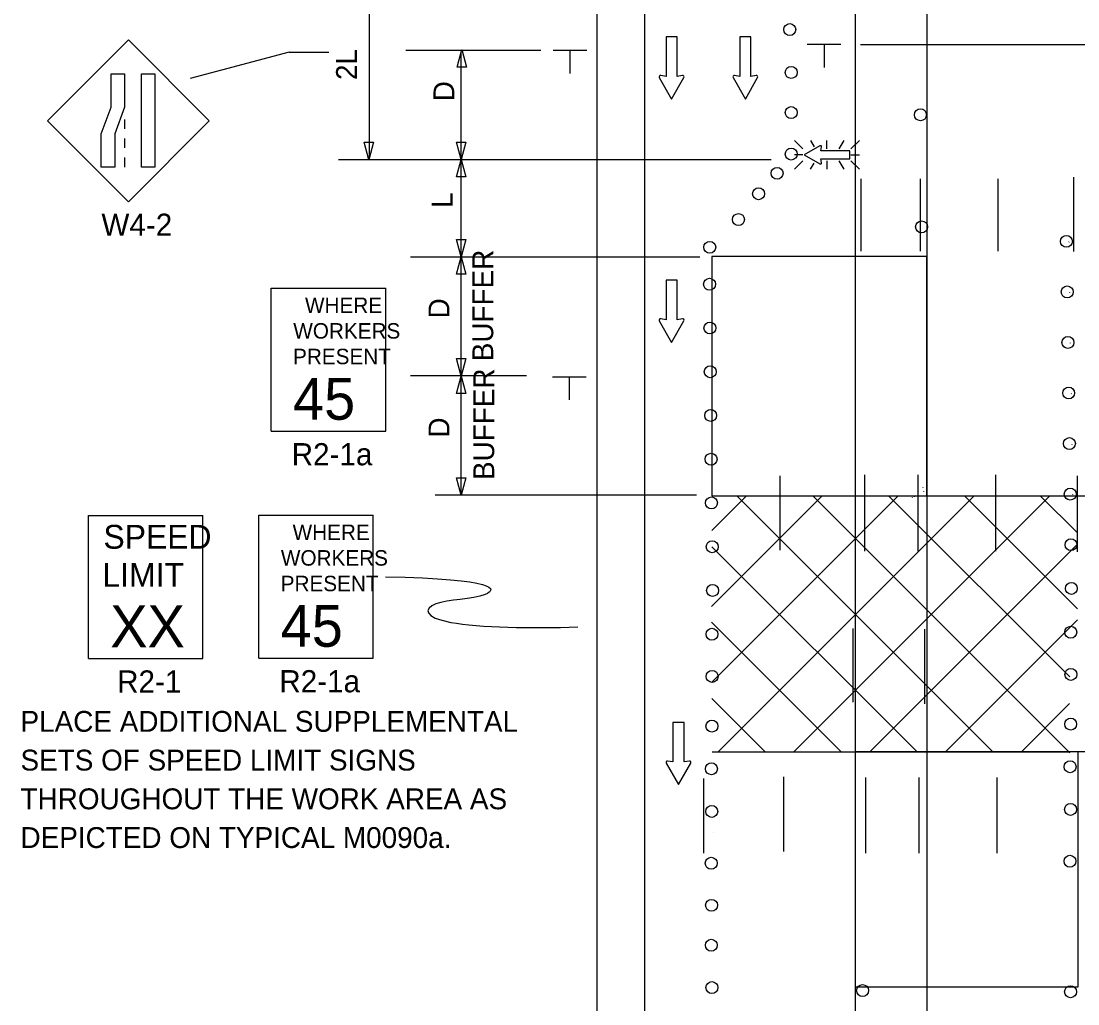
# Model space of a CAD drawing. Extents: x 20837 to 23689, y 414 to 2167.
# Drawn here: x 20920.2 to 21274.8, y 982.6 to 1312.5 of the extents above; entities that cross this region are included whole.
import ezdxf

# ---------------------------------------------------------------- set-up
doc = ezdxf.new("R2010")
doc.units = 0
for name, color, linetype in [('ALI_LEGAL_EX', 7, 'Continuous'), ('MT_SCRATCH_LEVEL_A', 7, 'Continuous'), ('MT_SCRATCH_LEVEL_E', 7, 'Continuous'), ('PAVT_EDGE_EX', 7, 'Continuous'), ('TRAFFIC_SIGNS_PR', 7, 'Continuous'), ('TYPICAL_EX', 7, 'Continuous'), ('TYPICAL_TEXT_DIMEN_PR', 7, 'Continuous')]:
    doc.layers.add(name, color=color, linetype=linetype)

msp = doc.modelspace()

# ---------------------------------------------------------------- linework, layer by layer
at = {"layer": 'ALI_LEGAL_EX'}
for points in [[(21202.17, 1235.29), (21202.17, 1259.59)], [(21222.04, 1235.29), (21222.04, 1259.59)], [(21248.14, 1235.29), (21248.14, 1259.59)], [(21273.46, 1235.24), (21273.46, 1260.18)], [(21174.97, 1134.9), (21174.97, 1159.91)], [(21203.3, 1134.6), (21203.3, 1160.28)], [(21221.19, 1134.6), (21221.19, 1160.28)], [(21247.3, 1134.6), (21247.3, 1160.28)], [(21274.69, 1134.35), (21274.69, 1159.87)], [(21199.44, 1083.89), (21199.44, 1108.68)], [(21223.52, 1083.41), (21223.52, 1108.45)], [(21149.27, 1033.22), (21149.27, 1058.33)], [(21176.19, 1033.74), (21176.19, 1058.85)], [(21203.73, 1033.25), (21203.73, 1058.65)], [(21221.63, 1033.25), (21221.63, 1058.65)], [(21247.73, 1033.25), (21247.73, 1058.65)]]:
    msp.add_lwpolyline(points, dxfattribs=at)
at = {"layer": 'MT_SCRATCH_LEVEL_A'}
for p, q in [((21271.86, 1238.33), (21271.91, 1238.45)), ((21272.12, 1221.36), (21272.17, 1221.47)), ((21272.37, 1204.39), (21272.42, 1204.5)), ((21272.62, 1187.41), (21272.67, 1187.53)), ((21272.87, 1170.44), (21272.92, 1170.56)), ((21151.91, 1116.01), (21189.07, 1153.17)), ((21152.01, 1153.17), (21272.32, 1153.17)), ((21152.01, 1141.56), (21163.62, 1153.17)), ((21152.04, 1090.69), (21214.53, 1153.17)), ((21154.08, 1067.27), (21239.99, 1153.17)), ((21246.32, 1067.27), (21160.41, 1153.17)), ((21179.53, 1067.27), (21265.44, 1153.17)), ((21272.1, 1066.94), (21185.87, 1153.17)), ((21272.12, 1092.38), (21211.32, 1153.17)), ((21219.19, 1152.6), (21219.24, 1152.52)), ((21219.88, 1152.95), (21219.93, 1152.88)), ((21221.47, 1154.78), (21221.52, 1154.7)), ((21222.92, 1155.91), (21222.97, 1156.02)), ((21223, 1154.64), (21223.05, 1154.56)), ((21224.35, 1153.2), (21224.35, 1153.17)), ((21274.69, 1115.26), (21236.78, 1153.17)), ((21274.69, 1140.71), (21262.23, 1153.17)), ((21273.12, 1153.47), (21273.18, 1153.59)), ((21220.86, 1067.27), (21152.01, 1136.12)), ((21204.99, 1067.27), (21274.69, 1136.97)), ((21195.41, 1067.27), (21151.92, 1110.75)), ((21230.45, 1067.27), (21274.69, 1111.52)), ((21169.95, 1067.27), (21152.01, 1085.2)), ((21255.9, 1067.27), (21272.07, 1083.43)), ((21152.06, 1067.27), (21272.02, 1067.27)), ((21152.47, 1040.2), (21152.47, 1040.2))]:
    msp.add_line(p, q, dxfattribs=at)
at = {"layer": 'MT_SCRATCH_LEVEL_E'}
for p, q in [((21140.37, 1307.21), (21136.63, 1307.21)), ((21136.63, 1307.21), (21136.63, 1293.95)), ((21140.37, 1307.21), (21136.63, 1307.21)), ((21136.63, 1307.21), (21136.63, 1293.95)), ((21140.37, 1293.95), (21140.37, 1307.21)), ((21140.37, 1293.95), (21140.37, 1307.21)), ((21165.11, 1307.21), (21161.36, 1307.21)), ((21161.36, 1307.21), (21161.36, 1293.95)), ((21165.11, 1307.21), (21161.36, 1307.21)), ((21161.36, 1307.21), (21161.36, 1293.95)), ((21165.11, 1293.95), (21165.11, 1307.21)), ((21165.11, 1293.95), (21165.11, 1307.21)), ((21134.37, 1293.59), (21138.52, 1286.34)), ((21134.37, 1293.59), (21138.52, 1286.34)), ((21136.63, 1293.95), (21134.85, 1294.27)), ((21136.63, 1293.95), (21134.85, 1294.27)), ((21138.52, 1286.34), (21142.63, 1293.59)), ((21138.52, 1286.34), (21142.63, 1293.59)), ((21142.15, 1294.27), (21140.37, 1293.95)), ((21142.15, 1294.27), (21140.37, 1293.95)), ((21159.11, 1293.59), (21163.25, 1286.34)), ((21159.11, 1293.59), (21163.25, 1286.34)), ((21161.36, 1293.95), (21159.59, 1294.27)), ((21161.36, 1293.95), (21159.59, 1294.27)), ((21163.25, 1286.34), (21167.36, 1293.59)), ((21163.25, 1286.34), (21167.36, 1293.59)), ((21166.88, 1294.27), (21165.11, 1293.95)), ((21166.88, 1294.27), (21165.11, 1293.95)), ((21140.37, 1225.58), (21136.63, 1225.58)), ((21136.63, 1225.58), (21136.63, 1212.32)), ((21140.37, 1225.58), (21136.63, 1225.58)), ((21136.63, 1225.58), (21136.63, 1212.32)), ((21140.37, 1212.32), (21140.37, 1225.58)), ((21140.37, 1212.32), (21140.37, 1225.58)), ((21134.37, 1211.95), (21138.52, 1204.71)), ((21134.37, 1211.95), (21138.52, 1204.71)), ((21136.63, 1212.32), (21134.85, 1212.64)), ((21136.63, 1212.32), (21134.85, 1212.64)), ((21138.52, 1204.71), (21142.63, 1211.95)), ((21138.52, 1204.71), (21142.63, 1211.95)), ((21142.15, 1212.64), (21140.37, 1212.32)), ((21142.15, 1212.64), (21140.37, 1212.32)), ((21142.68, 1077.11), (21138.94, 1077.11)), ((21138.94, 1077.11), (21138.94, 1063.85)), ((21142.68, 1077.11), (21138.94, 1077.11)), ((21138.94, 1077.11), (21138.94, 1063.85)), ((21142.68, 1063.85), (21142.68, 1077.11)), ((21142.68, 1063.85), (21142.68, 1077.11)), ((21138.94, 1063.85), (21137.17, 1064.16)), ((21138.94, 1063.85), (21137.17, 1064.16)), ((21144.46, 1064.16), (21142.68, 1063.85)), ((21144.46, 1064.16), (21142.68, 1063.85)), ((21136.69, 1063.48), (21140.83, 1056.24)), ((21136.69, 1063.48), (21140.83, 1056.24)), ((21140.83, 1056.24), (21144.94, 1063.48)), ((21140.83, 1056.24), (21144.94, 1063.48))]:
    msp.add_line(p, q, dxfattribs=at)
for centre, start, end in [((21134.78, 1293.81), 80.0362, 209.7731), ((21134.78, 1293.81), 80.0362, 209.7731), ((21142.22, 1293.81), 330.4248, 99.9638), ((21142.22, 1293.81), 330.4248, 99.9638), ((21159.52, 1293.81), 80.0362, 209.7731), ((21159.52, 1293.81), 80.0362, 209.7731), ((21166.96, 1293.81), 330.4248, 99.9638), ((21166.96, 1293.81), 330.4248, 99.9638), ((21134.78, 1212.18), 80.0362, 209.7731), ((21134.78, 1212.18), 80.0362, 209.7731), ((21142.22, 1212.18), 330.4248, 99.9638), ((21142.22, 1212.18), 330.4248, 99.9638), ((21137.09, 1063.7), 80.0362, 209.7731), ((21137.09, 1063.7), 80.0362, 209.7731), ((21144.54, 1063.71), 330.4248, 99.9638), ((21144.54, 1063.71), 330.4248, 99.9638)]:
    msp.add_arc(centre, 0.463, start, end, dxfattribs=at)
at = {"layer": 'PAVT_EDGE_EX'}
for p, q in [((21129.4, 1637.35), (21129.4, 813.35)), ((21200.14, 1637.05), (21200.14, 1162.94)), ((21224.14, 1637.05), (21224.14, 1153.29)), ((21200.14, 1162.94), (21200.14, 813.35)), ((21224.14, 1153.96), (21224.14, 813.35))]:
    msp.add_line(p, q, dxfattribs=at)
for points in [[(21224.14, 1233.54), (21152.01, 1233.54), (21152.01, 1153.17), (21224.14, 1153.17)], [(21274.98, 1067.27), (21200.14, 1067.27), (21200.14, 988.38), (21274.98, 988.38)]]:
    msp.add_lwpolyline(points, close=True, dxfattribs=at)
at = {"layer": 'TRAFFIC_SIGNS_PR'}
for p, q in [((20956.19, 1306.21), (20929.04, 1279.06)), ((20983.34, 1279.06), (20956.19, 1306.21)), ((20929.04, 1279.06), (20956.19, 1251.91)), ((20954.94, 1279.55), (20954.94, 1276.35)), ((20956.19, 1251.91), (20983.34, 1279.06)), ((20954.94, 1273.15), (20954.94, 1269.95)), ((21179.71, 1272.51), (21182.53, 1269.69)), ((21186.43, 1270.33), (21185.17, 1272.51)), ((21190.61, 1269.69), (21190.61, 1272.51)), ((21194.75, 1269.69), (21196.37, 1272.51)), ((21198.7, 1269.69), (21201.52, 1272.51)), ((20954.94, 1266.75), (20954.94, 1263.55)), ((21182.53, 1267.66), (21179.71, 1267.66)), ((21198.7, 1267.66), (21201.52, 1267.66)), ((21179.71, 1262.81), (21182.53, 1265.63)), ((21185.14, 1262.81), (21186.35, 1264.9)), ((21190.61, 1265.63), (21190.61, 1262.81)), ((21196.4, 1262.81), (21194.77, 1265.63)), ((21198.7, 1265.63), (21201.52, 1262.81)), ((21004.15, 1222.87), (21042.55, 1222.87)), ((21004.15, 1174.87), (21004.15, 1222.87)), ((21042.55, 1174.87), (21042.55, 1222.87)), ((21004.15, 1174.87), (21042.55, 1174.87)), ((20942.8, 1146.58), (20981.2, 1146.58)), ((20942.8, 1098.58), (20942.8, 1146.58)), ((20981.2, 1098.58), (20981.2, 1146.58)), ((21000, 1146.67), (21038.4, 1146.67)), ((21000, 1098.67), (21000, 1146.67)), ((21038.4, 1098.67), (21038.4, 1146.67)), ((20942.8, 1098.58), (20981.2, 1098.58)), ((21000, 1098.67), (21038.4, 1098.67))]:
    msp.add_line(p, q, dxfattribs=at)
for points in [[(20954.94, 1294.8), (20954.94, 1283.61), (20951.6, 1274.73), (20951.6, 1263.55), (20947.1, 1263.55), (20947.1, 1274.73), (20950.45, 1283.61), (20950.45, 1294.8)], [(20965.08, 1294.8), (20965.08, 1263.55), (20960.58, 1263.55), (20960.58, 1294.8)]]:
    msp.add_lwpolyline(points, close=True, dxfattribs=at)
for points in [[(21188.28, 1270.67), (21182.97, 1267.66), (21188.28, 1264.62)], [(21188.78, 1264.98), (21188.55, 1266.27), (21198.28, 1266.27), (21198.28, 1269.02), (21188.55, 1269.02), (21188.79, 1270.32)]]:
    msp.add_lwpolyline(points, dxfattribs=at)
for centre in [(21178.14, 1309.7), (21178.63, 1295.3), (21178.63, 1281.83), (21222.02, 1281.09), (21178.63, 1267.9), (21173.9, 1261.45), (21167.68, 1254.6), (21160.94, 1245.93), (21222.38, 1243.47), (21151.3, 1236.61), (21271, 1238.61), (21151.22, 1224.2), (21271.26, 1221.64), (21151.35, 1209.52), (21271.51, 1204.67), (21151.48, 1194.84), (21271.76, 1187.7), (21151.61, 1180.16), (21272.01, 1170.73), (21151.74, 1165.48), (21151.88, 1150.8), (21272.27, 1153.75), (21272.52, 1136.78), (21152.12, 1136.1), (21152.25, 1121.42), (21272.65, 1122.1), (21152.05, 1106.73), (21272.45, 1107.41), (21152.1, 1092.56), (21272.49, 1093.24), (21272.43, 1076.54), (21152.04, 1075.87), (21272.24, 1062.23), (21151.85, 1061.55), (21272.38, 1047.92), (21151.98, 1047.24), (21272.19, 1030.52), (21151.79, 1029.84), (21151.9, 1015.73), (21151.82, 1002.31), (21152.02, 988.1), (21202.6, 987.12), (21272.37, 986.72)]:
    msp.add_circle(centre, 2, dxfattribs=at)
for centre, start, end in [((21188.45, 1270.38), 350.7308, 118.8916), ((21188.45, 1264.92), 241.4833, 9.9593)]:
    msp.add_arc(centre, 0.341, start, end, dxfattribs=at)
at = {"layer": 'TYPICAL_EX'}
msp.add_line((21113.4, 1637.05), (21113.4, 813.35), dxfattribs=at)
at = {"layer": 'TYPICAL_TEXT_DIMEN_PR'}
for p, q in [((21037, 1323.28), (21037, 1266.41)), ((21010.2, 1302.14), (20976.89, 1293.3)), ((21010.2, 1302.14), (21023.48, 1302.14)), ((21049.32, 1302.76), (21094.58, 1302.76)), ((21066.49, 1297.13), (21068.06, 1302.99)), ((21067.83, 1266), (21067.83, 1302.31)), ((21068.06, 1302.99), (21069.63, 1297.13)), ((21098.77, 1302.76), (21110.02, 1302.76)), ((21104.39, 1302.76), (21104.39, 1294.98)), ((21184.02, 1304.78), (21195.27, 1304.78)), ((21189.65, 1304.78), (21189.65, 1296.99)), ((21359.37, 1304.61), (21201.93, 1304.61)), ((21068.06, 1297.13), (21066.49, 1297.13)), ((21069.63, 1297.13), (21068.06, 1297.13)), ((21036.88, 1265.99), (21035.31, 1271.85)), ((21035.31, 1271.85), (21036.88, 1271.85)), ((21036.88, 1271.85), (21038.45, 1271.85)), ((21038.45, 1271.85), (21036.88, 1265.99)), ((21067.84, 1266.09), (21066.27, 1271.95)), ((21066.27, 1271.95), (21067.84, 1271.95)), ((21067.84, 1271.95), (21069.41, 1271.95)), ((21069.41, 1271.95), (21067.84, 1266.09)), ((21026.68, 1266.11), (21171.95, 1266.11)), ((21066.27, 1260.27), (21067.84, 1266.13)), ((21067.84, 1266.13), (21069.41, 1260.27)), ((21067.83, 1233.42), (21067.83, 1265.7)), ((21067.84, 1260.27), (21066.27, 1260.27)), ((21069.41, 1260.27), (21067.84, 1260.27)), ((21067.84, 1233.41), (21066.27, 1239.27)), ((21066.27, 1239.27), (21067.84, 1239.27)), ((21067.84, 1239.27), (21069.41, 1239.27)), ((21069.41, 1239.27), (21067.84, 1233.41)), ((21050.82, 1233.41), (21147.94, 1233.41)), ((21066.27, 1227.55), (21067.84, 1233.41)), ((21067.84, 1193.41), (21067.84, 1233.41)), ((21067.84, 1233.41), (21069.41, 1227.55)), ((21067.84, 1227.55), (21066.27, 1227.55)), ((21069.41, 1227.55), (21067.84, 1227.55)), ((21067.84, 1193.41), (21066.27, 1199.27)), ((21066.27, 1199.27), (21067.84, 1199.27)), ((21067.84, 1199.27), (21069.41, 1199.27)), ((21069.41, 1199.27), (21067.84, 1193.41)), ((21050.82, 1193.54), (21089.8, 1193.54)), ((21066.27, 1187.55), (21067.84, 1193.41)), ((21067.84, 1153.41), (21067.84, 1193.41)), ((21067.84, 1193.41), (21069.41, 1187.55)), ((21098.55, 1193.18), (21109.8, 1193.18)), ((21104.17, 1193.18), (21104.17, 1185.4)), ((21067.84, 1187.55), (21066.27, 1187.55)), ((21069.41, 1187.55), (21067.84, 1187.55)), ((21067.84, 1153.41), (21066.27, 1159.27)), ((21066.27, 1159.27), (21067.84, 1159.27)), ((21067.84, 1159.27), (21069.41, 1159.27)), ((21069.41, 1159.27), (21067.84, 1153.41)), ((21059.19, 1153.54), (21146.91, 1153.54)), ((21272.32, 1153.17), (21363.75, 1153.17)), ((21365.67, 1067.27), (21200.14, 1067.27))]:
    msp.add_line(p, q, dxfattribs=at)
msp.add_open_spline([(21042.43, 1126.03), (21080.38, 1125.26), (21079.93, 1118.39), (21055.22, 1118.39), (21055.22, 1109.4), (21092.08, 1108.61), (21106.98, 1109.18)], degree=3, dxfattribs=at)

# ---------------------------------------------------------------- texts
at = {"layer": 'TRAFFIC_SIGNS_PR'}
for s, height, p in [('W4-2', 7.44, (20947.15, 1240.47)), ('WHERE', 5.2, (21015.46, 1214.56)), ('WORKERS', 5.2, (21011.53, 1205.96)), ('PRESENT', 5.2, (21011.46, 1197.36)), ('45', 14.031, (21011.45, 1178.73)), ('R2-1a', 7.44, (21011, 1163.43)), ('SPEED', 8, (20947.83, 1135.44)), ('WHERE', 5.2, (21011.31, 1138.35)), ('WORKERS', 5.2, (21007.38, 1129.75)), ('LIMIT', 8, (20947.5, 1122.64)), ('PRESENT', 5.2, (21007.31, 1121.15)), ('XX', 14.031, (20950.11, 1102.34)), ('45', 14.031, (21007.3, 1102.52)), ('R2-1', 7.44, (20952.41, 1087.14)), ('R2-1a', 7.44, (21006.85, 1087.23)), ('PLACE ADDITIONAL SUPPLEMENTAL', 7, (20920, 1073.97)), ('SETS OF SPEED LIMIT SIGNS', 7, (20920, 1060.97)), ('THROUGHOUT THE WORK AREA AS', 7, (20920, 1047.97)), ('DEPICTED ON TYPICAL M0090a.', 7, (20920, 1034.97))]:
    msp.add_text(s, height=height, dxfattribs=at).set_placement(p)
at = {"layer": 'TYPICAL_TEXT_DIMEN_PR'}
for s, p in [('2L', (21032.9, 1292.78)), ('D', (21065.57, 1285.63)), ('L', (21064.98, 1249.86)), ('BUFFER', (21078.64, 1198.37)), ('D', (21063.93, 1212.73)), ('BUFFER', (21078.97, 1158.5)), ('D', (21063.93, 1172.73))]:
    msp.add_text(s, height=7, rotation=90, dxfattribs=at).set_placement(p)

doc.saveas('drawing.dxf')
